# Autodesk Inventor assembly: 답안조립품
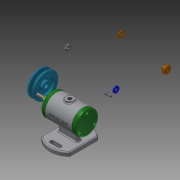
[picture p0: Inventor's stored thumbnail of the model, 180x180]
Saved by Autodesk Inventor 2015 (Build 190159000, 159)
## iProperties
Created: 2021-09
Part Number: 답안조립품
Document SubType Name: Assembly
Designer: 1019876
Author: 1019876
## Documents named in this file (14)
- C:\Users\1019876\Desktop\710906V1024\답안조립품.iam
- C:\Users\1019876\Desktop\710906V1024\V벨트풀리.ipt
- C:\Users\1019876\Desktop\710906V1024\너트 M8.ipt
- C:\Users\1019876\Desktop\710906V1024\뒤커버.ipt
- C:\Users\1019876\Desktop\710906V1024\베어링 15x32x9.ipt
- C:\Users\1019876\Desktop\710906V1024\본체.ipt
- C:\Users\1019876\Desktop\710906V1024\볼트 M4x12.ipt
- C:\Users\1019876\Desktop\710906V1024\스프링와셔 8.ipt
- C:\Users\1019876\Desktop\710906V1024\앞커버.ipt
- C:\Users\1019876\Desktop\710906V1024\오일 실 15x25x7.ipt
- C:\Users\1019876\Desktop\710906V1024\와셔 8x17.ipt
- C:\Users\1019876\Desktop\710906V1024\축.ipt
- C:\Users\1019876\Desktop\710906V1024\캡.ipt
- C:\Users\1019876\Desktop\710906V1024\키 3x3.ipt
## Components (1 placed, 1 different names)
1. V벨트풀리:1
